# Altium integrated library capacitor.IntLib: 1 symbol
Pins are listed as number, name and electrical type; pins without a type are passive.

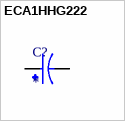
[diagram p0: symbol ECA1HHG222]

## ECA1HHG222
designator C?
Cap Aluminum 2200uF 50V 20% (16 X 31.5mm) Radial Aluminum Cylindrical Can 7.5mm 1470mA 2000 hr 105C Bulk; MF: Panasonic; MP: ECA1HHG222
footprint CAPPRD750W80D1600H3150
pins: N, P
